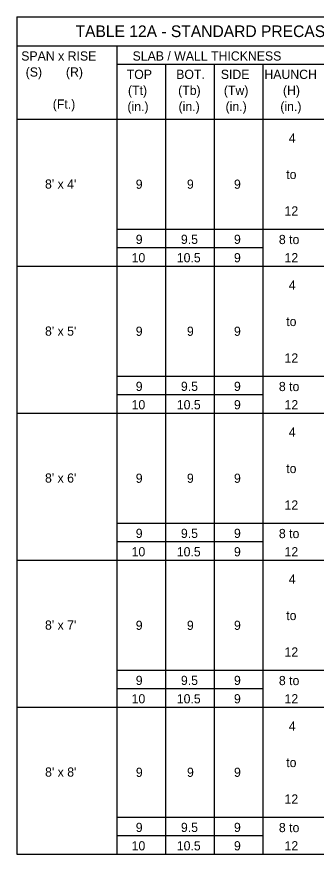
# Model space of a CAD drawing. Extents: x 10342.77 to 10344.98, y 76371.53 to 76372.62.
# Drawn here: x 10342.777 to 10342.983, y 76371.961 to 76372.535 of the extents above; entities that cross this region are included whole.
import ezdxf

# ---------------------------------------------------------------- set-up
doc = ezdxf.new("R2010")
doc.units = 0
doc.layers.add('AdhocPoint_dp', color=7, linetype='Continuous')
doc.layers.add('PlotBorder_dp', color=7, linetype='Continuous')

msp = doc.modelspace()

# ---------------------------------------------------------------- linework, layer by layer
at = {"layer": 'PlotBorder_dp'}
for p, q in [((10342.7771, 76372.53475), (10343.37184, 76372.53475)), ((10342.7771, 76372.53475), (10342.7771, 76371.96053)), ((10342.7771, 76372.51488), (10343.37184, 76372.51488)), ((10342.84574, 76372.51488), (10342.84574, 76371.96053)), ((10342.84574, 76372.50228), (10342.98818, 76372.50228)), ((10342.8791, 76372.50228), (10342.8791, 76371.96053)), ((10342.91246, 76372.50228), (10342.91246, 76371.96053)), ((10342.94582, 76372.50228), (10342.94582, 76371.96053)), ((10342.7771, 76372.46453), (10343.37184, 76372.46453)), ((10342.98818, 76372.38893), (10342.84574, 76372.38893)), ((10342.94582, 76372.37633), (10342.84574, 76372.37633)), ((10342.7771, 76372.36373), (10343.29445, 76372.36373)), ((10342.98818, 76372.28813), (10342.84574, 76372.28813)), ((10342.94582, 76372.27553), (10342.84574, 76372.27553)), ((10342.7771, 76372.26293), (10343.29445, 76372.26293)), ((10342.98818, 76372.18733), (10342.84574, 76372.18733)), ((10342.94582, 76372.17473), (10342.84574, 76372.17473)), ((10342.7771, 76372.16213), (10343.29445, 76372.16213)), ((10342.98818, 76372.08653), (10342.84574, 76372.08653)), ((10342.94582, 76372.07393), (10342.84574, 76372.07393)), ((10342.7771, 76372.06133), (10343.29445, 76372.06133)), ((10342.98818, 76371.98573), (10342.84574, 76371.98573)), ((10342.94582, 76371.97313), (10342.84574, 76371.97313)), ((10342.7771, 76371.96053), (10343.37184, 76371.96053))]:
    msp.add_line(p, q, dxfattribs=at)

# ---------------------------------------------------------------- texts
at = {"layer": 'AdhocPoint_dp'}
for s, height, p in [('TABLE 12A - STANDARD PRECAST BOX CULVERT DESIGNS (3" COVER) - 8\' SPANS', 0.008, (10342.81744, 76372.52081)), ('SLAB / WALL THICKNESS', 0.0063, (10342.85656, 76372.50472)), ('9', 0.0063, (10342.85875, 76372.4168)), ('9', 0.0063, (10342.89384, 76372.4168)), ('9', 0.0063, (10342.92613, 76372.4168)), ('9', 0.0063, (10342.85875, 76372.37898)), ('9.5', 0.0063, (10342.88973, 76372.37898)), ('9', 0.0063, (10342.92613, 76372.37898)), ('10', 0.0063, (10342.85591, 76372.36638)), ('10.5', 0.0063, (10342.8869, 76372.36638)), ('9', 0.0063, (10342.92613, 76372.36638)), ('9', 0.0063, (10342.85875, 76372.31597)), ('9', 0.0063, (10342.89384, 76372.31597)), ('9', 0.0063, (10342.92613, 76372.31597)), ('9', 0.0063, (10342.85875, 76372.27818)), ('9.5', 0.0063, (10342.88973, 76372.27818)), ('9', 0.0063, (10342.92613, 76372.27818)), ('10', 0.0063, (10342.85591, 76372.26558)), ('10.5', 0.0063, (10342.8869, 76372.26558)), ('9', 0.0063, (10342.92613, 76372.26558)), ('9', 0.0063, (10342.85875, 76372.21519)), ('9', 0.0063, (10342.89384, 76372.21519)), ('9', 0.0063, (10342.92613, 76372.21519)), ('9', 0.0063, (10342.85875, 76372.17738)), ('9.5', 0.0063, (10342.88973, 76372.17738)), ('9', 0.0063, (10342.92613, 76372.17738)), ('10', 0.0063, (10342.85591, 76372.16478)), ('10.5', 0.0063, (10342.8869, 76372.16478)), ('9', 0.0063, (10342.92613, 76372.16478)), ('9', 0.0063, (10342.85875, 76372.11435)), ('9', 0.0063, (10342.89384, 76372.11435)), ('9', 0.0063, (10342.92613, 76372.11435)), ('9', 0.0063, (10342.85875, 76372.07658)), ('9.5', 0.0063, (10342.88973, 76372.07658)), ('9', 0.0063, (10342.92613, 76372.07658)), ('10', 0.0063, (10342.85591, 76372.06398)), ('10.5', 0.0063, (10342.8869, 76372.06398)), ('9', 0.0063, (10342.92613, 76372.06398)), ('9', 0.0063, (10342.8588, 76372.01357)), ('9', 0.0063, (10342.89389, 76372.01357)), ('9', 0.0063, (10342.92618, 76372.01357)), ('9', 0.0063, (10342.85875, 76371.97578)), ('9.5', 0.0063, (10342.88973, 76371.97578)), ('9', 0.0063, (10342.92613, 76371.97578)), ('10', 0.0063, (10342.85591, 76371.96318)), ('10.5', 0.0063, (10342.8869, 76371.96318)), ('9', 0.0063, (10342.92613, 76371.96318))]:
    msp.add_text(s, height=height, dxfattribs=at).set_placement(p)
at = {"layer": 'PlotBorder_dp'}
for s, p in [('SPAN x RISE', (10342.78019, 76372.50472)), ('(S)       (R)', (10342.78323, 76372.49372)), ('TOP', (10342.85256, 76372.49212)), ('BOT.', (10342.88649, 76372.49212)), ('SIDE', (10342.91709, 76372.49212)), ('HAUNCH', (10342.94698, 76372.49212)), ('(Tt)', (10342.85341, 76372.48112)), ('(Tb)', (10342.88783, 76372.48112)), ('(Tw)', (10342.91919, 76372.48112)), ('(H)', (10342.95972, 76372.48112)), ('(Ft.)', (10342.80181, 76372.47172)), ('(in.)', (10342.85302, 76372.47012)), ('(in.)', (10342.88811, 76372.47012)), ('(in.)', (10342.92035, 76372.47012)), ('(in.)', (10342.95791, 76372.47012)), ('4', (10342.96376, 76372.44847)), ('to', (10342.96198, 76372.42347)), ("8' x 4'", (10342.79649, 76372.41691)), ('12', (10342.96081, 76372.39847)), ('8 to', (10342.95694, 76372.37888)), ('12', (10342.96081, 76372.36638)), ('4', (10342.96376, 76372.34767)), ('to', (10342.96198, 76372.32267)), ("8' x 5'", (10342.79649, 76372.31607)), ('12', (10342.96081, 76372.29767)), ('8 to', (10342.95694, 76372.27808)), ('12', (10342.96081, 76372.26558)), ('4', (10342.96376, 76372.24687)), ('to', (10342.96198, 76372.22187)), ("8' x 6'", (10342.79649, 76372.21535)), ('12', (10342.96081, 76372.19687)), ('8 to', (10342.95694, 76372.17728)), ('12', (10342.96081, 76372.16478)), ('4', (10342.96376, 76372.14607)), ('to', (10342.96198, 76372.12107)), ("8' x 7'", (10342.79649, 76372.11451)), ('12', (10342.96081, 76372.09607)), ('8 to', (10342.95694, 76372.07648)), ('12', (10342.96081, 76372.06398)), ('4', (10342.96376, 76372.04527)), ('to', (10342.96198, 76372.02027)), ("8' x 8'", (10342.79654, 76372.01373)), ('12', (10342.96081, 76371.99527)), ('8 to', (10342.95694, 76371.97568)), ('12', (10342.96081, 76371.96318))]:
    msp.add_text(s, height=0.0063, dxfattribs=at).set_placement(p)

doc.saveas('drawing.dxf')
